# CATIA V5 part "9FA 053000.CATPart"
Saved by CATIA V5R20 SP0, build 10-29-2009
Part number: 9FA 053000
Revision: ANY
Definition: UNKNOWN
Nomenclature: 9FA 053000
Source: Unknown
Bounding box of the stored display mesh (mm): x -2.5 to 2.5, y -6.775 to 5.225, z -2.5 to 2.5
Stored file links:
  C:\Users\Utente\Desktop\IO LAVORO\3D X SITO CF\CUMSA\3D files FA\FA 053000\9FA 053000.CATPart

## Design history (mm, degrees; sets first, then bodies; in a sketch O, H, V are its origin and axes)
Body1 "Cortar-Extruir2" (main body)
  Solid1: solid without history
